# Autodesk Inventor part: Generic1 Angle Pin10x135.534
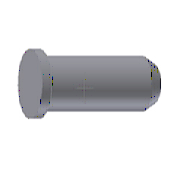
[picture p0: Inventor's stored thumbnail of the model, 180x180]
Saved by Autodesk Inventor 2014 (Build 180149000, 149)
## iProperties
IsCustomPart: 1
Created: 2009-11
Part Number: Generic1 Angle Pin10x135.534
Material: DIN 1.0401
Description: Guide Pillar
Document SubType Name: Modeling
Designer: gaom
Standard Revision: 1
Manufacturer: Generic
Language: en-US
Size Designation: 10x135.534
Categories: <MemberInstance><Categories><Category DisplayName="Mold" InternalName="349578f2-f4d4-4954-8c09-8e99297a61c0" Mnemonic="MOLD"><Category DisplayName="Slide Compon
Mass: 1.9988 g
Surface Area: 11.4076 cm^2
Volume: 1.9988 cm^3
Density: 7.82 g/cm^3
Appearance: Canary
Author: gaom
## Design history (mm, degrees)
sketch "Sketch1"
  geometry: L1 (0, -67.093)-(0, 17.015) reference; L2 (0, 5)-(-7, 5); L3 (-7, 5)-(-7, 0); L4 (-7, 0)-(-4.5, 0); L5 (-4.5, 0)-(-4.5, -1); L6 (-4.5, -1)-(-5, -1); L7 (-5, -1)-(-5, -126.534); L8 (-5, -126.534)-(-3.813, -130.189); L9 (-3.337, -130.534)-(0, -130.534); L10 (0, 5)-(0, -130.534); A1 r 0.5 centre (-3.337, -130.034) between (-3.813, -130.189) and (-3.337, -130.534); 3 further points
  constraints: 18 end point, 4 parallel, 4 point on line, 3 perpendicular, 2 point on circle, 2 tangent, 1 centre point, 1 collinear, 1 horizontal alignment, 1 midpoint
  dimensions: "d0" = 135.534 distance between parallel lines of L9 L2 (= AP_l); "d2" = 4 distance from line of L9 L7.end (= AP_l1); "d3" = 10 diameter of L7 L1 (= AP_d1); "d4" = 14 diameter of L3 L1 (= AP_d2); "d5" = 5 distance between parallel lines of L2 L4 (= AP_k); "d6" = 1 distance between parallel lines of L4 L6 (= AP_REF2); "d9" = 9 diameter of L5 L1 (= AP_d1 - AP_REF2); "d10" = 0.5 radius of A1 (= AP_REF1); "d15" = 18 deg angle of L7 L8 (= AP_REF4)
revolve "Revolution1" sketch "Sketch1" stored, may be unused: angle "d11" = 90 deg
fillet "Fillet1" dims "d42" = 0.3 (= AP_REF3)
node "AP_PP"
  workaxis "Work Axis1"
feature "Stitch Surface3" dims "d54" = 0.254 (derived)
feature "Sculpt6"
body "Solid1"
sketch "Sketch2"
  geometry: C1 r 5 at (0, 0) reference; 1 further point
body "Srf1"
body "Srf3"
sketch "Sketch3"
  geometry: C1 r 7 at (0, 0) reference; C2 r 7 at (0, 0); 1 further point
  constraints: 1 centre point, 1 coincident, 1 concentric
body "Srf2"
body "Srf4"
workplane "Work Plane1"
body "Srf5"
body "Srf6"
extrude_surface "ExtrusionSrf1" dims "d22" = 130.534 (= AP_l - AP_k), "d23" = 0
patch "Boundary Patch1" dims "d30" = 0, "d43" = 0
extrude_surface "ExtrusionSrf2" dims "d34" = 15 (= 3 x AP_k), "d35" = 0
patch "Boundary Patch2" dims "d38" = 0, "d47" = 0, "d48" = 0
patch "Boundary Patch3" dims "d52" = 0, "d53" = 0
other parameters: "AP_d1" = 10 [user parameter; used in 2 equation terms], "AP_l" = 135.534 [user parameter; used in 2 equation terms], "AP_d2" = 14 [user parameter; used in 1 equation term], "AP_k" = 5 [user parameter; used in 3 equation terms], "AP_l1" = 4 [user parameter; used in 1 equation term], "AP_ang" = 18 deg [user parameter; used in 1 equation term], "AP_REF1" = 0.5 [user parameter; used in 1 equation term], "AP_REF2" = 1 [user parameter; used in 2 equation terms], "AP_REF3" = 0.3 [user parameter; used in 1 equation term], "d44" = 0, "d45" = 18 deg (= AP_ang), "AP_REF4" = 18 deg [user parameter; used in 1 equation term]
